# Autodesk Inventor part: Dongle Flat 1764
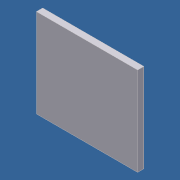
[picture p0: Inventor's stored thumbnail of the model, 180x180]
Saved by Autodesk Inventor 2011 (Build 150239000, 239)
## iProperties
Created: 2010-01
Part Number: Dongle Flat 1764
Document SubType Name: Modeling
Designer: jgehrig
Density: 1 g/cm^3
Author: jgehrig
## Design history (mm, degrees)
sketch "Sketch1"
  geometry: L1 (-3.179, 4.629)-(6.981, 4.629); L2 (6.981, 4.629)-(6.981, -4.261); L3 (6.981, -4.261)-(-3.179, -4.261); L4 (-3.179, -4.261)-(-3.179, 4.629); 1 further point
  constraints: 8 end point, 2 parallel, 1 horizontal, 1 perpendicular
  dimensions: "d0" = 8.89 distance of L1.end L2.end; "d1" = 10.16 distance of L2.end L3.end
extrude "Extrusion1" new body sketch "Sketch1" distance "d2" = 0.635; taper "d3" = 0 deg
body "Solid1"
